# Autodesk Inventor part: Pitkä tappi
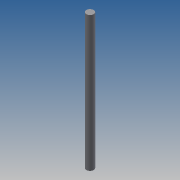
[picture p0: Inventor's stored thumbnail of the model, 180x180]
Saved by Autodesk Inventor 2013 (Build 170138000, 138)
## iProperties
Created: 2013-08
Part Number: Pitkä tappi
Material: Generic
Document SubType Name: Modeling
Designer: Reko Tuppurainen
Density: 1 g/cm^3
Author: Reko Tuppurainen
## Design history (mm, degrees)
sketch "Sketch1"
  geometry: C1 r 6 at (0, 0); 1 further point
  constraints: 1 centre point, 1 coincident
  dimensions: "d0" = 12 diameter of C1
extrude "Extrusion1" new body sketch "Sketch1" distance "d2" = 220; taper "d3" = 0 deg
body "Solid1"
